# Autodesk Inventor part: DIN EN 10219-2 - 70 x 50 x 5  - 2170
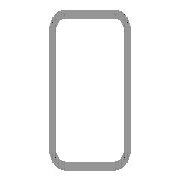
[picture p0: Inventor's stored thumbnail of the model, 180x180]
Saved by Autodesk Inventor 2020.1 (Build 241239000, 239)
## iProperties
_CCFamilyMember: 17
_CCFamilyDisplayName: DIN EN 10219-2 (Rechteckiges Hohlprofil - Kaltgeformt) - Kaltgeformte, geschweißte Baustahl-Hohlprofile aus unlegiertem Feinkorn-Baustahl
_FrameMemberDoc: Frame Member File
_Version: 15.0.0
_GetPNFromCC: 1
IsCustomPart: 1
Created: 2019-01
Part Number: DIN EN 10219-2 - 70 x 50 x 5  - 2170
Material: Stahl, weich
Description: Kaltgeformte, geschweißte Baustahl-Hohlprofile aus unlegiertem Feinkorn-Baustahl
Document SubType Name: Modeling
Standard: DIN
Designer: lutzd
Standard Revision: 2006-07
Standards Organization: DIN
Language: de-DE
Size Designation: 70 x 50 x 5
Categories: <MemberInstance><Categories><Category DisplayName="Profile" InternalName="089c4875-fa83-4c05-b084-43b9cc11f5ed" Mnemonic="GRDR"><CategoryParameter DisplayName="
Stock Number: 70 x 50 x 5
Mass: 17641.3 g
Surface Area: 9009.89 cm^2
Volume: 2247.29 cm^3
Density: 7.85 g/cm^3
Appearance: Semi-Polished(8)
G_W: 50,000 mm
G_H: 70,000 mm
Mass: 17,641 kg
VLT_Material: Stahl, weich
G_L: 2170,000 mm
Dimensions: 50x70x2170 mm
Author: lutzd
Revision Number: -
Title: Kaltgeformte, geschweißte Baustahl-Hohlprofile aus unlegiertem Feinkorn-Baustahl
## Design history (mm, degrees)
node "Startebene"
node "Endebene"
sketch "Skizze"
  geometry: L1 (-25, -25)-(-25, 25); L2 (-15, 35)-(15, 35); L3 (25, 25)-(25, -25); L4 (15, -35)-(-15, -35); L5 (-15, 30)-(15, 30); L6 (20, 25)-(20, -25); L7 (15, -30)-(-15, -30); L8 (-20, -25)-(-20, 25); L9 (0, 51.899)-(0, -51.899) reference; L10 (-37.899, 0)-(37.899, 0) reference; A1 r 10 centre (-15, -25) between (-25, -25) and (-15, -35); A2 r 10 centre (-15, 25) between (-15, 35) and (-25, 25); A3 r 10 centre (15, 25) between (25, 25) and (15, 35); A4 r 10 centre (15, -25) between (15, -35) and (25, -25); A5 r 5 centre (-15, 25) between (-15, 30) and (-20, 25); A6 r 5 centre (15, 25) between (20, 25) and (15, 30); A7 r 5 centre (15, -25) between (15, -30) and (20, -25); A8 r 5 centre (-15, -25) between (-20, -25) and (-15, -30)
  constraints: 16 end point, 16 point on circle, 8 centre point, 8 tangent, 4 parallel, 3 equal radius, 2 perpendicular, 7 other
  dimensions: "d7" = 10 radius of A1 (= G_IR); "d10" = 70 distance between parallel lines of L2 L4 (= G_H); "d11" = 50 distance between parallel lines of L1 L3 (= G_W); "d12" = 5 distance between parallel lines of L3 L6 (= G_T); "d15" = 35 distance between parallel lines of L2 L10 (= 0.5 x d10); "d16" = 25 distance between parallel lines of L9 L3 (= 0.5 x d11)
extrude "Körper" new body sketch "Skizze" stored distance "d3" = 2170 (= G_L); taper "d4" = 0 deg
node "Driven Length"
  sketch "Sketch3"
    geometry: L1 (0, 0)-(10, 0) reference
    constraints: 2 end point, 1 horizontal
  workplane "Work Plane3"
  sketch "Sketch4"
    geometry: L1 (-2, 0)-(12, 0) reference; L2 (-2, 2170)-(12, 2170) reference
    dimensions: "d18" = 2170 distance between parallel lines of L1 L2 (derived)
body "Solid1"
other parameters: "G_W" = 50 [user parameter; used in 1 equation term], "G_H" = 70 [user parameter; used in 1 equation term], "G_T" = 5 [user parameter; used in 1 equation term], "G_IR" = 10 [user parameter; used in 1 equation term], "G_L" = 2170 (= d18) [user parameter; used in 1 equation term], "G_OFFSET_START" = 0 [user parameter; used in 1 equation term], "G_OFFSET_END" = 0 [user parameter; used in 1 equation term], "d13" = 0 (computed from G_OFFSET_START), "d17" = 90 deg
